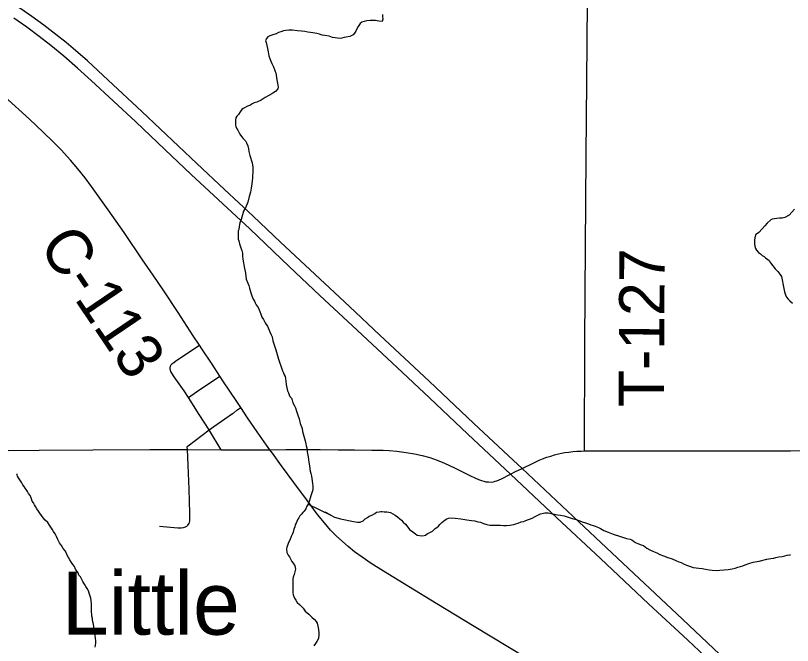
# Model space of a CAD drawing. Extents: x -17 to 88, y -5 to 22.
# Drawn here: x -14.955 to -13.981, y 17.501 to 18.289 of the extents above; entities that cross this region are included whole.
import ezdxf

# ---------------------------------------------------------------- set-up
doc = ezdxf.new("R2010")
doc.units = 0
for name, color, linetype in [('GM_X_County_Road', 7, 'Continuous'), ('GM_X_County_Road_Text', 7, 'Continuous'), ('GM_X_Minor_River', 7, 'Continuous'), ('GM_X_State_Route', 7, 'Continuous'), ('GM_X_Township_Road', 7, 'Continuous'), ('GM_X_Township_Road_Text', 7, 'Continuous'), ('GM_X_Township_Subdivision', 7, 'Continuous'), ('GM_X_Unincorporated_Text', 7, 'Continuous'), ('GM_X_US_Route', 7, 'Continuous')]:
    doc.layers.add(name, color=color, linetype=linetype)

msp = doc.modelspace()

# ---------------------------------------------------------------- linework, layer by layer
at = {"layer": 'GM_X_County_Road'}
for points in [[(-14.72434, 17.87666), (-14.7323, 17.88854), (-14.75121, 17.91776), (-14.76907, 17.94467), (-14.78233, 17.96421), (-14.79562, 17.98374), (-14.81879, 18.01757), (-14.83863, 18.04615), (-14.85954, 18.07548), (-14.86774, 18.0864), (-14.87667, 18.09752), (-14.88598, 18.10832), (-14.89776, 18.12109), (-14.90769, 18.13133), (-14.92012, 18.14348), (-14.93733, 18.15962), (-14.9687, 18.18793), (-14.97842, 18.19663), (-14.9894, 18.20667)], [(-14.69876, 17.83798), (-14.70862, 17.85281), (-14.72123, 17.87202), (-14.72434, 17.87666)], [(-14.67267, 17.79882), (-14.67757, 17.80629), (-14.69485, 17.8321), (-14.69876, 17.83798)], [(-14.6361, 17.74567), (-14.64022, 17.75125), (-14.65202, 17.76804), (-14.66394, 17.78551), (-14.67267, 17.79882)], [(-14.18693, 17.40687), (-14.27068, 17.4581), (-14.3158, 17.48557), (-14.38015, 17.52448), (-14.42691, 17.55287), (-14.46238, 17.57468), (-14.49371, 17.59375), (-14.50897, 17.60337), (-14.52029, 17.61109), (-14.52987, 17.61804), (-14.5382, 17.6246), (-14.5453, 17.6307), (-14.55303, 17.63795), (-14.55997, 17.64514), (-14.56772, 17.6541), (-14.57626, 17.66482), (-14.58899, 17.6817), (-14.60605, 17.70463), (-14.62169, 17.72555), (-14.63284, 17.74126), (-14.6361, 17.74567)]]:
    msp.add_lwpolyline(points, dxfattribs=at)
at = {"layer": 'GM_X_Minor_River'}
for points in [[(-14.49498, 18.2909), (-14.49498, 18.28825), (-14.4946, 18.28483), (-14.49536, 18.28179), (-14.49953, 18.28255), (-14.5037, 18.28331), (-14.50712, 18.28331), (-14.51053, 18.28331), (-14.51471, 18.28293), (-14.51774, 18.28217), (-14.52078, 18.28103), (-14.52305, 18.27951), (-14.52533, 18.27571), (-14.52722, 18.27267), (-14.52836, 18.27001), (-14.53026, 18.26735), (-14.53178, 18.26508), (-14.53595, 18.26318), (-14.54051, 18.26242), (-14.54316, 18.26204), (-14.54582, 18.26128), (-14.54809, 18.26052), (-14.55758, 18.26204), (-14.56175, 18.26355), (-14.56744, 18.26431), (-14.57048, 18.26507), (-14.5739, 18.26621), (-14.57731, 18.26697), (-14.57997, 18.26735), (-14.58224, 18.26773), (-14.58528, 18.26811), (-14.58869, 18.26849), (-14.59249, 18.26925), (-14.59666, 18.27), (-14.60159, 18.27039), (-14.60767, 18.27114), (-14.61222, 18.27114), (-14.61601, 18.27076), (-14.61905, 18.27038), (-14.62246, 18.26924), (-14.62512, 18.2681), (-14.62815, 18.26658), (-14.63233, 18.26544), (-14.63612, 18.26392), (-14.63878, 18.26278), (-14.64029, 18.26051), (-14.64143, 18.25785), (-14.64067, 18.25557), (-14.63991, 18.25177), (-14.63915, 18.24797), (-14.63839, 18.2438), (-14.63725, 18.23886), (-14.63497, 18.23241), (-14.63346, 18.22937), (-14.63232, 18.22709), (-14.63156, 18.22519), (-14.63042, 18.22178), (-14.62928, 18.2195), (-14.62852, 18.2176), (-14.62814, 18.21494), (-14.62776, 18.2119), (-14.62738, 18.20886), (-14.62662, 18.20469), (-14.62624, 18.20241), (-14.62586, 18.19975), (-14.62624, 18.19747), (-14.6289, 18.19443), (-14.63117, 18.19292), (-14.63345, 18.19139), (-14.63724, 18.1895)], [(-14.63724, 18.1895), (-14.64217, 18.18684), (-14.6471, 18.18342), (-14.65242, 18.18114), (-14.65583, 18.18), (-14.65849, 18.17886), (-14.66038, 18.17734), (-14.66418, 18.17582), (-14.66721, 18.1743), (-14.66949, 18.17316), (-14.67138, 18.17164), (-14.67328, 18.16899), (-14.67556, 18.16557), (-14.67745, 18.16329), (-14.67859, 18.16139), (-14.67897, 18.15835), (-14.67935, 18.15532), (-14.67897, 18.15228), (-14.67859, 18.15038), (-14.67745, 18.14772), (-14.67631, 18.14582), (-14.67517, 18.14354), (-14.67365, 18.14089), (-14.67175, 18.13785), (-14.66948, 18.13557), (-14.66682, 18.13253), (-14.6653, 18.13025), (-14.66378, 18.12608), (-14.66302, 18.12266), (-14.66226, 18.11924), (-14.66112, 18.11431), (-14.65847, 18.10481), (-14.65771, 18.10253), (-14.65733, 18.0995), (-14.65733, 18.0976), (-14.65732, 18.09494), (-14.65732, 18.0919), (-14.6577, 18.08962), (-14.65808, 18.08583), (-14.65846, 18.08241), (-14.65884, 18.07861), (-14.65959, 18.0733), (-14.66035, 18.06836), (-14.66187, 18.06266), (-14.66376, 18.05583), (-14.6668, 18.04861), (-14.66907, 18.04443), (-14.67021, 18.03988), (-14.67211, 18.03418), (-14.67362, 18.03), (-14.674, 18.02772), (-14.67438, 18.02545), (-14.67514, 18.02165), (-14.6759, 18.01975), (-14.6759, 18.01519), (-14.67589, 18.01254), (-14.67589, 18.0095), (-14.67513, 18.00722), (-14.674, 18.00342), (-14.67323, 18.00114), (-14.67248, 17.99849), (-14.67134, 17.99507), (-14.67058, 17.99203), (-14.6702, 17.98861), (-14.66982, 17.98444), (-14.66906, 17.97988), (-14.6683, 17.97494), (-14.66677, 17.96697), (-14.66564, 17.95938), (-14.66374, 17.95444), (-14.6626, 17.9514), (-14.66146, 17.94798), (-14.6607, 17.94495), (-14.65994, 17.94229), (-14.6588, 17.93849), (-14.6569, 17.93431), (-14.65538, 17.93166), (-14.65462, 17.92976), (-14.65311, 17.9271), (-14.65083, 17.92368), (-14.64969, 17.92102), (-14.64855, 17.91875), (-14.64741, 17.91533), (-14.64627, 17.91191), (-14.64399, 17.90887), (-14.6421, 17.9047), (-14.64058, 17.90242), (-14.63906, 17.90052), (-14.6383, 17.89824), (-14.63678, 17.89558), (-14.63602, 17.8933), (-14.63488, 17.89065), (-14.63336, 17.88723), (-14.63222, 17.88229), (-14.63033, 17.87584), (-14.6288, 17.8709), (-14.62539, 17.85913), (-14.62387, 17.85533), (-14.62197, 17.84964), (-14.62045, 17.8447), (-14.61893, 17.84204)], [(-13.97849, 18.04681), (-13.98532, 18.03959), (-13.99063, 18.03655), (-13.99404, 18.03579), (-13.99746, 18.03579), (-14.00088, 18.03541), (-14.00391, 18.03503), (-14.00657, 18.03427), (-14.00847, 18.03351), (-14.01302, 18.02934), (-14.01567, 18.02592), (-14.01909, 18.0225), (-14.02326, 18.01756), (-14.02743, 18.0149), (-14.02857, 18.01111), (-14.02895, 18.00807), (-14.02895, 18.00579), (-14.02895, 18.00351), (-14.02857, 18.00047), (-14.02743, 17.99782), (-14.02629, 17.99554), (-14.02363, 17.99288), (-14.02135, 17.99098), (-14.01908, 17.98908), (-14.0168, 17.98756), (-14.0149, 17.98604), (-14.01225, 17.98415), (-14.01035, 17.98263), (-14.00883, 17.97997), (-14.00579, 17.97617), (-14.00276, 17.97238), (-13.99972, 17.96896), (-13.99706, 17.96554), (-13.99478, 17.9625), (-13.99212, 17.9477), (-13.99136, 17.94352), (-13.98985, 17.93972), (-13.98871, 17.93668), (-13.98643, 17.93441), (-13.98453, 17.93213), (-13.98112, 17.92947)], [(-14.61893, 17.84204), (-14.61817, 17.83939), (-14.61703, 17.83749), (-14.61665, 17.83483), (-14.6159, 17.83179), (-14.61551, 17.82761), (-14.61476, 17.82344), (-14.61399, 17.81964), (-14.61285, 17.81698), (-14.6121, 17.81432), (-14.61096, 17.81242), (-14.60906, 17.81015), (-14.6083, 17.80787), (-14.60716, 17.80445), (-14.60564, 17.80142), (-14.60412, 17.79838), (-14.60261, 17.7942), (-14.60108, 17.78889), (-14.59919, 17.78433), (-14.59805, 17.77863), (-14.59653, 17.77446), (-14.59577, 17.77218), (-14.59501, 17.76876), (-14.59425, 17.76572), (-14.59349, 17.76268), (-14.59273, 17.75965), (-14.59197, 17.75699), (-14.59121, 17.75319), (-14.59045, 17.75053), (-14.58969, 17.74825), (-14.58931, 17.74294), (-14.58817, 17.73686), (-14.58741, 17.73003), (-14.58665, 17.72547), (-14.58589, 17.72167), (-14.58551, 17.71902), (-14.58475, 17.71598), (-14.58399, 17.71256), (-14.58361, 17.7099), (-14.58323, 17.70686), (-14.58285, 17.70307), (-14.58247, 17.70041), (-14.58247, 17.69547), (-14.58398, 17.69053), (-14.58474, 17.68788), (-14.5855, 17.68522), (-14.58702, 17.68104), (-14.58815, 17.67763), (-14.58967, 17.67497), (-14.59119, 17.67155), (-14.59308, 17.66889), (-14.59498, 17.66699), (-14.5965, 17.66509), (-14.5984, 17.66281), (-14.59991, 17.66053), (-14.60105, 17.65864), (-14.60219, 17.65598), (-14.60333, 17.6537), (-14.60446, 17.6518), (-14.60484, 17.64914), (-14.60598, 17.6461), (-14.60674, 17.64269), (-14.60787, 17.64041), (-14.60939, 17.63699), (-14.61129, 17.63243), (-14.6128, 17.6294), (-14.61394, 17.62598), (-14.6147, 17.6237), (-14.61508, 17.62104), (-14.6147, 17.61725), (-14.61318, 17.61383), (-14.61166, 17.61155), (-14.60976, 17.60813), (-14.60862, 17.60585), (-14.60711, 17.60357), (-14.60483, 17.60054), (-14.60407, 17.59598), (-14.60558, 17.58953), (-14.6071, 17.58611), (-14.60748, 17.58421), (-14.60748, 17.57016), (-14.60747, 17.56674), (-14.60672, 17.56408), (-14.6052, 17.55991), (-14.60368, 17.55725), (-14.60178, 17.55459), (-14.59912, 17.55193), (-14.59685, 17.55003), (-14.59457, 17.54738), (-14.59191, 17.54358), (-14.58736, 17.53978), (-14.58356, 17.53599), (-14.58015, 17.53295), (-14.57825, 17.53067), (-14.57673, 17.52839), (-14.57559, 17.52308), (-14.57483, 17.517), (-14.57483, 17.51396), (-14.57521, 17.50941), (-14.5771, 17.50561), (-14.579, 17.50295)], [(-14.85485, 17.49836), (-14.85447, 17.50101), (-14.85409, 17.50367), (-14.85409, 17.50633), (-14.85447, 17.50975), (-14.85485, 17.51317), (-14.85523, 17.51658), (-14.85637, 17.52076), (-14.85675, 17.52494), (-14.85751, 17.52911), (-14.85827, 17.53177), (-14.85827, 17.53443), (-14.85903, 17.53747), (-14.85941, 17.54013), (-14.85979, 17.54202), (-14.85979, 17.5443), (-14.85979, 17.5481), (-14.85979, 17.5519), (-14.86018, 17.55683), (-14.86055, 17.55987), (-14.86245, 17.56633), (-14.86359, 17.56899), (-14.86511, 17.57202), (-14.86663, 17.5743), (-14.86777, 17.5762), (-14.86929, 17.57848), (-14.87043, 17.58075), (-14.87157, 17.58303), (-14.87346, 17.58645), (-14.87536, 17.58873), (-14.8765, 17.59139), (-14.87802, 17.59367), (-14.87954, 17.59632), (-14.88106, 17.59936), (-14.88295, 17.60202), (-14.88485, 17.60468), (-14.88675, 17.60771), (-14.88865, 17.61075), (-14.89017, 17.61379), (-14.89206, 17.61873), (-14.8951, 17.62214), (-14.89738, 17.62594), (-14.89965, 17.62936), (-14.90193, 17.63315), (-14.90345, 17.63695), (-14.90535, 17.64037), (-14.90725, 17.64341), (-14.90877, 17.64606), (-14.91066, 17.64872), (-14.91218, 17.65138), (-14.91446, 17.65442), (-14.9175, 17.65745), (-14.92015, 17.66049), (-14.92243, 17.66353), (-14.92433, 17.66619), (-14.92623, 17.66885), (-14.92812, 17.67188), (-14.92964, 17.67454), (-14.93116, 17.67682), (-14.9323, 17.6791), (-14.93382, 17.68137), (-14.93496, 17.68441), (-14.93648, 17.68859), (-14.93837, 17.69087), (-14.93989, 17.69353), (-14.94141, 17.6958), (-14.94293, 17.6977), (-14.94407, 17.6996), (-14.94559, 17.70188), (-14.94672, 17.70416), (-14.9509, 17.71061), (-14.95242, 17.71251), (-14.9528, 17.71441), (-14.95318, 17.71517), (-14.95242, 17.71555)], [(-14.58815, 17.67763), (-14.55969, 17.66396), (-14.5669, 17.66737), (-14.55969, 17.66396), (-14.55514, 17.6613), (-14.54755, 17.6594), (-14.53123, 17.65599), (-14.5263, 17.65523), (-14.52288, 17.65523), (-14.51909, 17.65675), (-14.51682, 17.65903), (-14.51378, 17.66093), (-14.51151, 17.66245), (-14.50923, 17.66321), (-14.50733, 17.66435), (-14.50467, 17.66586), (-14.5024, 17.66738), (-14.49898, 17.66814), (-14.49709, 17.66852), (-14.49519, 17.66852), (-14.49291, 17.66814), (-14.4895, 17.66814), (-14.48722, 17.66739), (-14.48494, 17.66701), (-14.48191, 17.66549), (-14.47925, 17.66359), (-14.47622, 17.66169), (-14.47318, 17.65941), (-14.47128, 17.65751), (-14.46901, 17.65486), (-14.46597, 17.65258), (-14.46445, 17.6503), (-14.46103, 17.64575), (-14.45686, 17.64309), (-14.45382, 17.64043), (-14.45155, 17.63891), (-14.44851, 17.63815), (-14.44547, 17.63777), (-14.44282, 17.63815), (-14.44092, 17.63891), (-14.43902, 17.64043), (-14.4322, 17.64385), (-14.42878, 17.64727), (-14.42689, 17.64841), (-14.42461, 17.64992), (-14.42309, 17.65221), (-14.42082, 17.65448), (-14.41854, 17.65638), (-14.41664, 17.6579), (-14.41437, 17.65904), (-14.41209, 17.66018), (-14.40792, 17.66056), (-14.40374, 17.66018), (-14.39691, 17.65904), (-14.38933, 17.6579), (-14.38325, 17.65715), (-14.37908, 17.65677), (-14.37566, 17.65563), (-14.37225, 17.65487), (-14.36845, 17.65335), (-14.36428, 17.65221), (-14.36048, 17.65146), (-14.35631, 17.65107), (-14.35403, 17.65107), (-14.35062, 17.65108), (-14.3472, 17.65107), (-14.34341, 17.6507), (-14.33961, 17.6507), (-14.33544, 17.65108), (-14.33279, 17.65184), (-14.33051, 17.65222), (-14.32785, 17.65298), (-14.32482, 17.65374), (-14.3214, 17.65526), (-14.31837, 17.65602), (-14.31609, 17.65678), (-14.31344, 17.65792), (-14.31078, 17.65868), (-14.30736, 17.66019), (-14.30357, 17.66209), (-14.30016, 17.66399), (-14.29712, 17.66551), (-14.29484, 17.66589), (-14.29143, 17.66665), (-14.28726, 17.66665), (-14.27549, 17.66438), (-14.27208, 17.66362), (-14.26752, 17.66286), (-14.26221, 17.66134), (-14.25728, 17.65982), (-14.25235, 17.6583), (-14.24779, 17.65678), (-14.24476, 17.65565), (-14.24058, 17.65413), (-14.23679, 17.65299), (-14.23375, 17.65185), (-14.2311, 17.65071), (-14.22844, 17.64995), (-14.22654, 17.64919), (-14.22426, 17.64843), (-14.22161, 17.64692)], [(-14.22161, 17.64692), (-14.21743, 17.64464), (-14.21212, 17.64236), (-14.20605, 17.64008), (-14.19656, 17.63705), (-14.18935, 17.63477), (-14.1848, 17.63363), (-14.18252, 17.63287), (-14.18062, 17.63135), (-14.17797, 17.62946), (-14.17417, 17.62794), (-14.17076, 17.6268), (-14.1681, 17.62566), (-14.16582, 17.62414), (-14.16354, 17.62262), (-14.16013, 17.62034), (-14.15558, 17.61845), (-14.1514, 17.61655), (-14.14723, 17.61465), (-14.14267, 17.61275), (-14.13736, 17.61085), (-14.13205, 17.60896), (-14.1275, 17.60706), (-14.1237, 17.60554), (-14.12066, 17.6044), (-14.11763, 17.60288), (-14.11421, 17.60136), (-14.1089, 17.59947), (-14.10549, 17.59833), (-14.10207, 17.59795), (-14.09865, 17.59757), (-14.09448, 17.59681), (-14.09031, 17.59605), (-14.08575, 17.59529), (-14.08196, 17.59491), (-14.07475, 17.59453), (-14.07209, 17.59491), (-14.06678, 17.59529), (-14.06185, 17.59567), (-14.05692, 17.59644), (-14.05312, 17.59757), (-14.04971, 17.59871), (-14.04629, 17.59948), (-14.04363, 17.60023), (-14.0406, 17.60175), (-14.03605, 17.60327), (-14.03036, 17.60479), (-14.02277, 17.60631), (-14.01328, 17.60859), (-14.00835, 17.60973), (-14.00455, 17.61011), (-14.0019, 17.61087), (-13.99811, 17.61163), (-13.99431, 17.61201), (-13.9909, 17.61277), (-13.98786, 17.61391), (-13.98483, 17.61429), (-13.98369, 17.61429)], [(-14.579, 17.50295), (-14.5809, 17.50029)]]:
    msp.add_lwpolyline(points, dxfattribs=at)
at = {"layer": 'GM_X_State_Route'}
for points in [[(-15.99637, 17.73721), (-15.91634, 17.73806), (-15.72744, 17.73971), (-15.66283, 17.74052), (-15.59012, 17.74092), (-15.3919, 17.74205), (-15.24315, 17.74333), (-15.21417, 17.74357), (-15.13961, 17.74381), (-15.00352, 17.74445), (-14.92522, 17.74529), (-14.85811, 17.74575), (-14.78666, 17.74604), (-14.73951, 17.74607)], [(-14.73951, 17.74607), (-14.69715, 17.74579), (-14.6361, 17.74567), (-14.61611, 17.7459)], [(-14.61611, 17.7459), (-14.6147, 17.74592), (-14.59668, 17.74596), (-14.57308, 17.74599), (-14.55072, 17.74554), (-14.53022, 17.7455), (-14.50849, 17.74528), (-14.50515, 17.74524)], [(-14.50515, 17.74524), (-14.49423, 17.74511), (-14.48682, 17.74474), (-14.47696, 17.74385), (-14.46527, 17.74242), (-14.45489, 17.74072), (-14.44521, 17.73868), (-14.43569, 17.73607), (-14.42636, 17.73279), (-14.41721, 17.72901), (-14.40487, 17.72322), (-14.3849, 17.71305), (-14.37924, 17.71042), (-14.37461, 17.70836), (-14.37105, 17.70709), (-14.36801, 17.70619), (-14.3655, 17.70574), (-14.36225, 17.70537), (-14.35872, 17.70529), (-14.356, 17.7057), (-14.3537, 17.70628), (-14.35164, 17.70695), (-14.34885, 17.70809), (-14.34583, 17.70946), (-14.33468, 17.71528), (-14.32818, 17.71832), (-14.32001, 17.72212)], [(-14.32001, 17.72212), (-14.30544, 17.72947), (-14.29878, 17.73252), (-14.29451, 17.73433), (-14.28908, 17.73622), (-14.28423, 17.73779), (-14.27946, 17.73919), (-14.27445, 17.7405), (-14.27058, 17.74132), (-14.26639, 17.74207), (-14.26129, 17.74281), (-14.25661, 17.74339), (-14.25143, 17.7438), (-14.24592, 17.74413), (-14.24188, 17.74432), (-14.2327, 17.74455), (-14.22987, 17.74453)], [(-14.22987, 17.74453), (-14.20785, 17.74439), (-14.1749, 17.7443), (-14.0562, 17.74444), (-13.98349, 17.74451), (-13.88717, 17.74466)]]:
    msp.add_lwpolyline(points, dxfattribs=at)
at = {"layer": 'GM_X_Township_Road'}
msp.add_lwpolyline([(-14.24188, 17.74432), (-14.24138, 17.87773), (-14.24096, 17.94173), (-14.24013, 18.05669), (-14.23974, 18.11387), (-14.23874, 18.20769), (-14.23817, 18.30588), (-14.23813, 18.38355), (-14.23821, 18.41649), (-14.23835, 18.45341)], dxfattribs=at)
at = {"layer": 'GM_X_Township_Subdivision'}
for points in [[(-14.76066, 17.85009), (-14.76001, 17.85161), (-14.75951, 17.85247), (-14.75889, 17.85325), (-14.75774, 17.85424), (-14.75655, 17.85514), (-14.75393, 17.8571), (-14.72434, 17.87666)], [(-14.73826, 17.81095), (-14.74335, 17.81931), (-14.75602, 17.83692), (-14.75907, 17.84158), (-14.76013, 17.84361), (-14.7608, 17.84542), (-14.76107, 17.84659), (-14.76116, 17.84774), (-14.76099, 17.84893), (-14.76066, 17.85009)], [(-14.73826, 17.81095), (-14.72809, 17.81824), (-14.69876, 17.83798)], [(-14.71222, 17.77048), (-14.7249, 17.78992), (-14.73826, 17.81095)], [(-14.68297, 17.79104), (-14.68137, 17.79215), (-14.67743, 17.79518), (-14.67267, 17.79882)], [(-14.71222, 17.77048), (-14.70639, 17.77482), (-14.69259, 17.78436), (-14.68297, 17.79104)], [(-14.73951, 17.74607), (-14.73968, 17.74912), (-14.73927, 17.75017), (-14.73857, 17.75081), (-14.71222, 17.77048)], [(-14.69715, 17.74579), (-14.71169, 17.76967), (-14.71222, 17.77048)], [(-14.73733, 17.65346), (-14.7367, 17.65524), (-14.73642, 17.65651), (-14.73629, 17.65838), (-14.73641, 17.66648), (-14.73727, 17.69639), (-14.73858, 17.72626), (-14.73951, 17.74607)], [(-14.77431, 17.64989), (-14.75586, 17.64822), (-14.75154, 17.64797), (-14.74721, 17.64796), (-14.74417, 17.64837), (-14.74186, 17.64917), (-14.74029, 17.65013), (-14.73895, 17.65121), (-14.73733, 17.65346)]]:
    msp.add_lwpolyline(points, dxfattribs=at)
at = {"layer": 'GM_X_US_Route'}
for points in [[(-14.32001, 17.72212), (-14.33142, 17.7328), (-14.38039, 17.77872), (-14.43655, 17.83149), (-14.49828, 17.88925), (-14.53635, 17.92496), (-14.62263, 18.0056), (-14.65699, 18.03802), (-14.69282, 18.07159), (-14.72776, 18.1043), (-14.79651, 18.16909), (-14.83872, 18.20858), (-14.8648, 18.23254), (-14.87967, 18.24571), (-14.89154, 18.25571), (-14.90413, 18.26579), (-14.91943, 18.27745), (-14.93452, 18.28837), (-14.94832, 18.29788), (-14.96548, 18.30908)], [(-14.07666, 17.4737), (-14.11253, 17.50724), (-14.16168, 17.55296), (-14.22184, 17.60964), (-14.27634, 17.66054), (-14.33468, 17.71528), (-14.38783, 17.76516), (-14.43622, 17.81076), (-14.4766, 17.84859), (-14.53236, 17.90087), (-14.57332, 17.93897), (-14.61181, 17.97515), (-14.6614, 18.02221), (-14.73461, 18.09043), (-14.76759, 18.12157), (-14.8042, 18.15614), (-14.8601, 18.2083), (-14.87718, 18.22373), (-14.89412, 18.23838), (-14.91043, 18.25185), (-14.92515, 18.26333), (-14.9407, 18.27475), (-14.95704, 18.28614)], [(-14.07276, 17.48982), (-14.12613, 17.54012), (-14.18022, 17.59057), (-14.24881, 17.65553), (-14.32001, 17.72212)]]:
    msp.add_lwpolyline(points, dxfattribs=at)

# ---------------------------------------------------------------- texts
at = {"layer": 'GM_X_County_Road_Text'}
msp.add_text('C-113', height=0.056818, rotation=304.06371, dxfattribs=at).set_placement((-14.92688, 18.00139))
at = {"layer": 'GM_X_Township_Road_Text'}
msp.add_text('T-127', height=0.056818, rotation=89.7281, dxfattribs=at).set_placement((-14.1423, 17.79909))
at = {"layer": 'GM_X_Unincorporated_Text'}
msp.add_text('Little', height=0.078977, rotation=0.00001, dxfattribs=at).set_placement((-14.89675, 17.51412))

doc.saveas('drawing.dxf')
